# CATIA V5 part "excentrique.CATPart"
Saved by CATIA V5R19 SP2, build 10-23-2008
Part number: excentrique
Bounding box of the stored display mesh (mm): x 0 to 69, y -72.897 to 87.103, z -70.141 to 89.486
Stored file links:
  C:\Documents and Settings\jboiteux\Bureau\iao_jboiteux\Catia\non optiisé\iao final\excentrique.CATPart
  C:\iao4\mecanisme a rouleaux.CATProduct
  C:\Documents and Settings\jboiteux\Bureau\iao_jboiteux\Catia\non optiisé\iao final\bati.CATPart
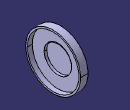
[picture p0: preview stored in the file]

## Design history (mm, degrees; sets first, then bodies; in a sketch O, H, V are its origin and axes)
Parameters
  entraxe = 12 mm
  taille = 10 mm {= External.taille}
External parameters (linked from other documents)
  External.taille = 10 mm
Body1 (main body)
  Sketch1 on yz-plane, origin (0, 0, 0), H (0, 1, 0), V (0, 0, 1)
    circle A1 centre (0, 0) radius 15
    radius A1 = 15 {= taille *1.5}
  Pad1: profile Sketch1, direction (1, 0, 0), length 40 {= taille  *4}
  Sketch2 on end face of Pad1, origin (40, 0, 0), H (0, 1, 0), V (0, 0, 1)
    circle A1 centre (0, 0) radius 40
    radius A1 = 40 {= taille *4}
  Pad2: profile Sketch2, direction (1, 0, 0), length 7.5 {= taille  *0.75}
  Sketch3 on end face of Pad2, origin (47.5, 0, 0), H (0, 1, 0), V (0, 0, 1)
    circle A1 centre (7.1028, 9.6722) radius 40
    point P1 (7.1028, 9.6722)
    circle A2 centre (7.1028, 9.6722) radius 80
    radius A2 = 80 {= taille *8}
    radius A1 = 40 {= taille *4}
    distance P1 O = 12 {= entraxe}
  Pad3: profile Sketch3, direction (1, 0, 0), length 1.5 {= `détruit_LENGTH` *0.75}
  Sketch4 on end face of Pad3, origin (49, 0, 0), H (0, 1, 0), V (0, 0, 1)
    projected circle E1 centre (7.1028, 9.6722) radius 80 from edge [face of Pad3 from Sketch3.A2 | end face of Pad3]
    circle A1 centre (7.1028, 9.6722) radius 75
    radius A1 = 75 {= taille *7.5}
    concentricity: A1 E1
  Pad4: profile Sketch4, direction (1, 0, 0), length 20 {= taille *2}
  Sketch5 on start face of Pad3, origin (47.5, 0, 0), H (0, 1, 0), V (0, 0, 1)
    circle A1 centre (7.1028, 9.6722) radius 40
    point P1 (7.1028, 9.6722)
    circle A2 centre (7.1028, 9.6722) radius 80
    radius A2 = 80 {= taille *8}
    radius A1 = 40 {= taille  *4}
    distance P1 O = 12 {= entraxe}
  Pad5: profile Sketch5, direction (1, 0, 0), length 7.5 {= taille  *0.75}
